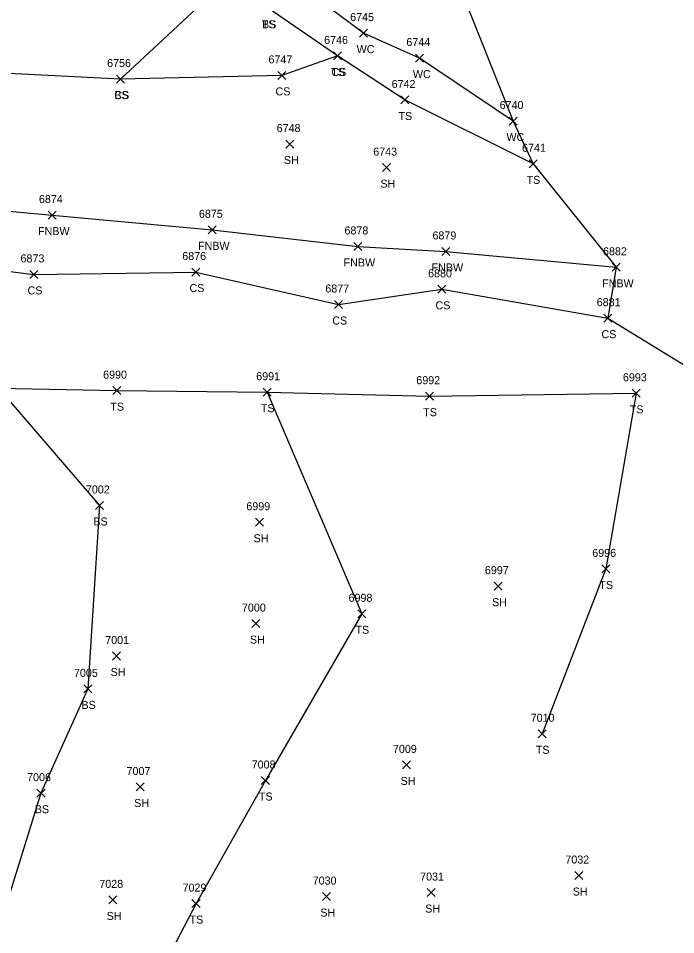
# Model space of a CAD drawing. Extents: x 1472233 to 1475777, y 540726 to 543442.
# Drawn here: x 1472796.8 to 1472960.9, y 541249 to 541477.9 of the extents above; entities that cross this region are included whole.
import ezdxf

# ---------------------------------------------------------------- set-up
doc = ezdxf.new("R2010")
doc.units = 0
for name, color, linetype in [('L_A', 7, 'Continuous'), ('L_I', 7, 'Continuous'), ('L_TIC', 7, 'Continuous'), ('LAWE', 7, 'Continuous'), ('LELB', 7, 'Continuous'), ('LFNC', 7, 'Continuous'), ('LSOGP', 7, 'Continuous')]:
    doc.layers.add(name, color=color, linetype=linetype)

msp = doc.modelspace()

# ---------------------------------------------------------------- linework, layer by layer
at = {"layer": 'L_TIC'}
for points in [[(1472881.95, 541473.17), (1472883.95, 541475.17)], [(1472883.95, 541473.17), (1472881.95, 541475.17)], [(1472875.51, 541467.46), (1472877.51, 541469.46)], [(1472877.51, 541467.46), (1472875.51, 541469.46)], [(1472875.51, 541467.46), (1472877.51, 541469.46)], [(1472877.51, 541467.46), (1472875.51, 541469.46)], [(1472895.98, 541466.95), (1472897.98, 541468.95)], [(1472897.98, 541466.95), (1472895.98, 541468.95)], [(1472821.32, 541461.69), (1472823.32, 541463.69)], [(1472823.32, 541461.69), (1472821.32, 541463.69)], [(1472821.32, 541461.69), (1472823.32, 541463.69)], [(1472823.32, 541461.69), (1472821.32, 541463.69)], [(1472861.55, 541462.62), (1472863.55, 541464.62)], [(1472863.55, 541462.62), (1472861.55, 541464.62)], [(1472892.29, 541456.47), (1472894.29, 541458.47)], [(1472894.29, 541456.47), (1472892.29, 541458.47)], [(1472919.36, 541451.21), (1472921.36, 541453.21)], [(1472921.36, 541451.21), (1472919.36, 541453.21)], [(1472863.6, 541445.46), (1472865.6, 541447.46)], [(1472865.6, 541445.46), (1472863.6, 541447.46)], [(1472924.3, 541440.52), (1472926.3, 541442.52)], [(1472926.3, 541440.52), (1472924.3, 541442.52)], [(1472887.7, 541439.57), (1472889.7, 541441.57)], [(1472889.7, 541439.57), (1472887.7, 541441.57)], [(1472804.24, 541427.72), (1472806.24, 541429.72)], [(1472806.24, 541427.72), (1472804.24, 541429.72)], [(1472844.19, 541424.04), (1472846.19, 541426.04)], [(1472846.19, 541424.04), (1472844.19, 541426.04)], [(1472880.53, 541419.88), (1472882.53, 541421.88)], [(1472882.53, 541419.88), (1472880.53, 541421.88)], [(1472902.5, 541418.64), (1472904.5, 541420.64)], [(1472904.5, 541418.64), (1472902.5, 541420.64)], [(1472799.65, 541412.9), (1472801.65, 541414.9)], [(1472801.65, 541412.9), (1472799.65, 541414.9)], [(1472840.08, 541413.5), (1472842.08, 541415.5)], [(1472842.08, 541413.5), (1472840.08, 541415.5)], [(1472945.07, 541414.68), (1472947.07, 541416.68)], [(1472947.07, 541414.68), (1472945.07, 541416.68)], [(1472901.49, 541409.18), (1472903.49, 541411.18)], [(1472903.49, 541409.18), (1472901.49, 541411.18)], [(1472875.74, 541405.38), (1472877.74, 541407.38)], [(1472877.74, 541405.38), (1472875.74, 541407.38)], [(1472942.94, 541401.97), (1472944.94, 541403.97)], [(1472944.94, 541401.97), (1472942.94, 541403.97)], [(1472820.36, 541383.87), (1472822.36, 541385.87)], [(1472822.36, 541383.87), (1472820.36, 541385.87)], [(1472857.93, 541383.48), (1472859.93, 541385.48)], [(1472859.93, 541383.48), (1472857.93, 541385.48)], [(1472857.93, 541383.48), (1472859.93, 541385.48)], [(1472859.93, 541383.48), (1472857.93, 541385.48)], [(1472950.04, 541383.21), (1472952.04, 541385.21)], [(1472952.04, 541383.21), (1472950.04, 541385.21)], [(1472898.46, 541382.48), (1472900.46, 541384.48)], [(1472900.46, 541382.48), (1472898.46, 541384.48)], [(1472816.08, 541355.19), (1472818.08, 541357.19)], [(1472818.08, 541355.19), (1472816.08, 541357.19)], [(1472856.03, 541351), (1472858.03, 541353)], [(1472858.03, 541351), (1472856.03, 541353)], [(1472942.44, 541339.34), (1472944.44, 541341.34)], [(1472944.44, 541339.34), (1472942.44, 541341.34)], [(1472915.59, 541335.03), (1472917.59, 541337.03)], [(1472917.59, 541335.03), (1472915.59, 541337.03)], [(1472881.55, 541328.13), (1472883.55, 541330.13)], [(1472883.55, 541328.13), (1472881.55, 541330.13)], [(1472855.12, 541325.68), (1472857.12, 541327.68)], [(1472857.12, 541325.68), (1472855.12, 541327.68)], [(1472820.34, 541317.59), (1472822.34, 541319.59)], [(1472822.34, 541317.59), (1472820.34, 541319.59)], [(1472813.11, 541309.37), (1472815.11, 541311.37)], [(1472815.11, 541309.37), (1472813.11, 541311.37)], [(1472926.57, 541298.16), (1472928.57, 541300.16)], [(1472928.57, 541298.16), (1472926.57, 541300.16)], [(1472892.74, 541290.39), (1472894.74, 541292.39)], [(1472894.74, 541290.39), (1472892.74, 541292.39)], [(1472826.23, 541284.87), (1472828.23, 541286.87)], [(1472828.23, 541284.87), (1472826.23, 541286.87)], [(1472857.46, 541286.49), (1472859.46, 541288.49)], [(1472859.46, 541286.49), (1472857.46, 541288.49)], [(1472801.45, 541283.33), (1472803.45, 541285.33)], [(1472803.45, 541283.33), (1472801.45, 541285.33)], [(1472935.71, 541262.75), (1472937.71, 541264.75)], [(1472937.71, 541262.75), (1472935.71, 541264.75)], [(1472872.7, 541257.5), (1472874.7, 541259.5)], [(1472874.7, 541257.5), (1472872.7, 541259.5)], [(1472898.88, 541258.5), (1472900.88, 541260.5)], [(1472900.88, 541258.5), (1472898.88, 541260.5)], [(1472819.35, 541256.67), (1472821.35, 541258.67)], [(1472821.35, 541256.67), (1472819.35, 541258.67)], [(1472840.15, 541255.75), (1472842.15, 541257.75)], [(1472842.15, 541255.75), (1472840.15, 541257.75)]]:
    msp.add_lwpolyline(points, dxfattribs=at)
at = {"layer": 'LAWE'}
msp.add_lwpolyline([(1472920.36, 541452.21), (1472896.98, 541467.95), (1472882.95, 541474.17), (1472870.99, 541483.19)], dxfattribs=at)
at = {"layer": 'LELB'}
for points in [[(1472925.3, 541441.52), (1472893.29, 541457.47), (1472876.51, 541468.46), (1472859.18, 541480.37), (1472847.04, 541490.77), (1472827.54, 541484.24), (1472811.01, 541499.69), (1472805.78, 541497.18), (1472802.28, 541501.03), (1472791.31, 541499.16), (1472786.29, 541486.35), (1472750.99, 541467.45), (1472730.71, 541457.67), (1472709.45, 541450.77), (1472703.66, 541440.64), (1472706.25, 541436.83), (1472719.38, 541434.8), (1472725.03, 541427.37), (1472722.95, 541421.12), (1472713.49, 541412.17), (1472709.9, 541412.71), (1472705.59, 541412.81)], [(1472859.18, 541480.37), (1472846.2, 541484.97), (1472822.32, 541462.69), (1472791.01, 541464.29), (1472753.8, 541459.11), (1472732.89, 541452.92), (1472720.17, 541445.11), (1472719.38, 541434.8)], [(1472876.51, 541468.46), (1472862.55, 541463.62), (1472822.32, 541462.69)], [(1472705.37, 541396.52), (1472725.62, 541406.45), (1472760.69, 541418.94), (1472800.65, 541413.9), (1472841.08, 541414.5), (1472876.74, 541406.38), (1472902.49, 541410.18), (1472943.94, 541402.97)], [(1472701.54, 541300.28), (1472722.38, 541305.92), (1472755.56, 541311.16), (1472754.67, 541333.3), (1472750.2, 541351.84), (1472737.24, 541375.61), (1472755.85, 541384.94), (1472791.79, 541385.49), (1472821.36, 541384.87), (1472858.93, 541384.48), (1472899.46, 541383.48), (1472951.04, 541384.21), (1472943.44, 541340.34), (1472927.57, 541299.16)], [(1472791.79, 541385.49), (1472817.08, 541356.19), (1472814.11, 541310.37), (1472802.45, 541284.33), (1472793.63, 541256.08), (1472760.15, 541210.36), (1472751.82, 541168.92)], [(1472858.93, 541384.48), (1472882.55, 541329.13), (1472858.46, 541287.49), (1472841.15, 541256.75), (1472828.3, 541232.05), (1472814.45, 541211.24), (1472803.09, 541188.07), (1472801.69, 541165.01), (1472813.32, 541134.73), (1472826.65, 541101.53), (1472835.7, 541066.92), (1472845.77, 541044.66)]]:
    msp.add_lwpolyline(points, dxfattribs=at)
at = {"layer": 'LFNC'}
msp.add_lwpolyline([(1472718.92, 541419.5), (1472722.95, 541421.12), (1472730.6, 541424.22), (1472759.36, 541432.91), (1472805.24, 541428.72), (1472845.19, 541425.04), (1472881.53, 541420.88), (1472903.5, 541419.64), (1472946.07, 541415.68)], dxfattribs=at)
at = {"layer": 'LSOGP'}
msp.add_lwpolyline([(1472823.77, 541743.14), (1472826.55, 541708.8), (1472845.91, 541656.61), (1472853.28, 541632.51), (1472849.75, 541618.72), (1472854.12, 541609.84), (1472858.88, 541602.25), (1472860.79, 541600.3), (1472863.45, 541597.21), (1472864.77, 541595.77), (1472874.51, 541579.29), (1472881.95, 541566.38), (1472885.31, 541541.17), (1472897.73, 541515.17), (1472898.91, 541507.88), (1472902.55, 541496.99), (1472920.36, 541452.21), (1472925.3, 541441.52), (1472946.07, 541415.68), (1472943.94, 541402.97), (1472977.95, 541382.17)], dxfattribs=at)

# ---------------------------------------------------------------- texts
at = {"layer": 'L_A'}
for s, p in [('TS', (1472857.59, 541475.37)), ('BS', (1472857.62, 541475.37)), ('WC', (1472881.26, 541469.17)), ('TS', (1472874.91, 541463.46)), ('CS', (1472874.95, 541463.46)), ('WC', (1472895.29, 541462.95)), ('CS', (1472861, 541458.62)), ('CS', (1472820.76, 541457.69)), ('BS', (1472820.76, 541457.69)), ('TS', (1472891.7, 541452.47)), ('WC', (1472918.66, 541447.21)), ('SH', (1472863.09, 541441.46)), ('SH', (1472887.19, 541435.57)), ('TS', (1472923.7, 541436.52)), ('FNBW', (1472801.71, 541423.72)), ('FNBW', (1472841.66, 541420.04)), ('FNBW', (1472878, 541415.88)), ('FNBW', (1472899.97, 541414.64)), ('FNBW', (1472942.55, 541410.68)), ('CS', (1472799.09, 541408.9)), ('CS', (1472839.52, 541409.5)), ('CS', (1472900.94, 541405.18)), ('CS', (1472875.19, 541401.38)), ('CS', (1472942.38, 541397.97)), ('TS', (1472819.77, 541379.87)), ('TS', (1472857.33, 541379.48)), ('TS', (1472857.33, 541379.48)), ('TS', (1472897.87, 541378.48)), ('TS', (1472949.45, 541379.21)), ('BS', (1472815.52, 541351.19)), ('SH', (1472855.52, 541347)), ('TS', (1472941.85, 541335.34)), ('SH', (1472915.08, 541331.03)), ('TS', (1472880.96, 541324.13)), ('SH', (1472854.61, 541321.68)), ('SH', (1472819.83, 541313.59)), ('BS', (1472812.55, 541305.37)), ('TS', (1472925.98, 541294.16)), ('SH', (1472892.23, 541286.39)), ('TS', (1472856.87, 541282.49)), ('SH', (1472825.72, 541280.87)), ('BS', (1472800.89, 541279.33)), ('SH', (1472935.2, 541258.75)), ('SH', (1472818.84, 541252.67)), ('SH', (1472872.19, 541253.5)), ('SH', (1472898.37, 541254.5)), ('TS', (1472839.56, 541251.75))]:
    msp.add_text(s, height=2, dxfattribs=at).set_placement(p)
at = {"layer": 'L_I'}
for s, p in [('6745', (1472879.64, 541477.17)), ('6746', (1472873.14, 541471.46)), ('6746', (1472873.14, 541471.46)), ('6744', (1472893.67, 541470.95)), ('6756', (1472818.96, 541465.69)), ('6756', (1472818.96, 541465.69)), ('6747', (1472859.25, 541466.62)), ('6742', (1472889.99, 541460.47)), ('6740', (1472916.96, 541455.21)), ('6748', (1472861.29, 541449.46)), ('6743', (1472885.4, 541443.57)), ('6741', (1472922.55, 541444.52)), ('6874', (1472801.93, 541431.72)), ('6875', (1472841.88, 541428.04)), ('6878', (1472878.22, 541423.88)), ('6879', (1472900.19, 541422.64)), ('6876', (1472837.72, 541417.5)), ('6882', (1472942.77, 541418.68)), ('6873', (1472797.34, 541416.9)), ('6880', (1472899.1, 541413.18)), ('6877', (1472873.44, 541409.38)), ('6881', (1472941.2, 541405.97)), ('6990', (1472817.96, 541387.87)), ('6991', (1472856.19, 541387.48)), ('6991', (1472856.19, 541387.48)), ('6992', (1472896.16, 541386.48)), ('6993', (1472947.74, 541387.21)), ('7002', (1472813.66, 541359.19)), ('6999', (1472853.72, 541355)), ('6996', (1472940.08, 541343.34)), ('6997', (1472913.28, 541339.03)), ('6998', (1472879.24, 541332.13)), ('7000', (1472852.62, 541329.68)), ('7001', (1472818.49, 541321.59)), ('7005', (1472810.69, 541313.37)), ('7010', (1472924.71, 541302.16)), ('7009', (1472890.32, 541294.39)), ('7008', (1472855.05, 541290.49)), ('7006', (1472798.98, 541287.33)), ('7007', (1472823.81, 541288.87)), ('7032', (1472933.37, 541266.75)), ('7031', (1472897.11, 541262.5)), ('7028', (1472817.01, 541260.67)), ('7029', (1472837.8, 541259.75)), ('7030', (1472870.28, 541261.5))]:
    msp.add_text(s, height=2, dxfattribs=at).set_placement(p)

doc.saveas('drawing.dxf')
